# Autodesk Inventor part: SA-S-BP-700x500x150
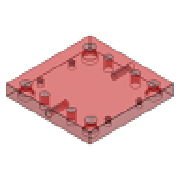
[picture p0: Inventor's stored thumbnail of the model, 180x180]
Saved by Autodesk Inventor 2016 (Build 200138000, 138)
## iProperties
IsCustomPart: 1
Created: 2015-02
Part Number: SA-S-BP-700x500x150
Material: S 55 C
Description: Core Plate
Document SubType Name: Modeling
Designer: Sandeep
Standard Revision: 1
Manufacturer: FUTABA
Language: en-US
Size Designation: 700x500x150
Categories: <MemberInstance><Categories><Category DisplayName="Mold" InternalName="349578f2-f4d4-4954-8c09-8e99297a61c0" Mnemonic="MOLD"><Category DisplayName="Mold Plates"
Density: 7.85 g/cm^3
Appearance: Dark Red
Author: Sandeep
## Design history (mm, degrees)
sketch "Sketch1"
  geometry: L1 (-250, 350)-(250, 350); L2 (250, 350)-(250, -350); L3 (250, -350)-(-250, -350); L4 (-250, -350)-(-250, 350); 7 further points
  constraints: 8 end point, 2 horizontal alignment, 2 midpoint, 2 parallel, 1 horizontal, 1 perpendicular, 1 vertical alignment
  dimensions: "d123" = 500 distance between parallel lines of L2 L4 (= W_); "d124" = 700 distance between parallel lines of L3 L1 (= L); "d125" = 317 vertical distance of point (0, 0) point (-128, 317) (= 0.5 x RP_L); "d126" = 128 horizontal distance of point (0, 0) point (-128, 317) (= 0.5 x RP_W); "d127" = 207 horizontal distance of point (0, 0) point (-207, 307) (= 0.5 x GP_W); "d128" = 307 vertical distance of point (0, 0) point (-207, 307) (= 0.5 x GP_L); "d129" = 205 horizontal distance of point (0, 0) point (-205, 243) (= 0.5 x S1_W); "d130" = 243 vertical distance of point (0, 0) point (-205, 243) (= 0.5 x S1_L); "d140" = 207 horizontal distance of point (207, 307) point (0, 0) (= 0.5 x GP_W)
extrude "Extrusion1" new body sketch "Sketch1" distance "d20" = 150 (= H_); taper "d30" = 0 deg
feature "Sculpt4"
body "Solid1"
sketch "Sketch2"
  geometry: L1 (500, 0)-(0, 0) reference; 3 further points
  constraints: 1 midpoint, 1 vertical alignment
  dimensions: "d186" = 75 distance from line of L1 point (250, 75) (= 0.5 x H_)
hole "Hole1" sketch "Sketch2" diameter "d104" = 31.67; stored, may be unused: countersink angle "d108" = 90 deg, drill point angle "d110" = 118 deg; dims "d105" = 59 (= le), "d106" = 46 (= GP_d2), "d107" = 10 (= GP_k), "d109" = 82 (= ke)
sketch "Sketch3"
  geometry: L1 (0, 0)-(500, 0) reference; 3 further points
  constraints: 1 midpoint, 1 vertical alignment
  dimensions: "d187" = 75 distance from line of point (250, -75) L1 (= 0.5 x H_)
hole "Hole2" sketch "Sketch3" diameter "d113" = 31.67; stored, may be unused: countersink angle "d117" = 90 deg, drill point angle "d119" = 118 deg; dims "d114" = 59 (= le), "d115" = 46 (= GP_d2), "d116" = 10 (= GP_k), "d118" = 82 (= ke)
hole "Hole3" sketch "Sketch1" diameter "d131" = 13.835; stored, may be unused: countersink angle "d135" = 90 deg, drill point angle "d137" = 118 deg; dims "d132" = 20 (= H_l), "d133" = 4, "d134" = 2, "d136" = 30 (= H_u)
pattern_linear "Rectangular Pattern1" dims "d164" = 243 (computed from S1_L, Ns)
hole "Hole4" sketch "Sketch1" diameter "d141" = 40 (= GP_d1); stored, may be unused: countersink angle "d145" = 90 deg, drill point angle "d147" = 0 deg; dims "d142" = 6, "d143" = 46 (= GP_d2), "d144" = 10 (= GP_k), "d146" = 150 (= H_)
pattern_linear "Rectangular Pattern2" dims "d170" = 614 (computed from GP_L, Nl)
hole "Hole5" sketch "Sketch1" diameter "d148" = 40 (= GP_d1); stored, may be unused: countersink angle "d152" = 90 deg, drill point angle "d154" = 0 deg; dims "d149" = 6, "d150" = 46 (= GP_d2), "d151" = 10 (= GP_k), "d153" = 150 (= H_)
pattern_linear "Rectangular Pattern3" dims "d173" = 612 (computed from GP_L2, GP_L1, Nl)
hole "Hole6" sketch "Sketch1" diameter "d155" = 30 (= RP_dt); stored, may be unused: countersink angle "d159" = 90 deg, drill point angle "d161" = 0 deg; dims "d156" = 6, "d157" = 46 (= GP_d2), "d158" = 10 (= GP_k), "d160" = 150 (= H_)
pattern_linear "Rectangular Pattern4" dims "d176" = 634 (computed from RP_L, Nl), "d179" = 256 (computed from RP_W, Nw)
chamfer "Chamfer1" distance "d180" = 0.5; stored, may be unused: second distance "d181" = 2, angle "d182" = 45 deg
feature "Surface4"
body "Srf4"
other parameters: "L" = 700 [user parameter; used in 1 equation term], "W_" = 500 [user parameter; used in 3 equation terms], "H_" = 150 [user parameter; used in 8 equation terms], "GP_W" = 414 [user parameter; used in 2 equation terms], "GP_d1" = 40 [user parameter; used in 2 equation terms], "GP_d2" = 46 [user parameter; used in 5 equation terms], "GP_k" = 10 [user parameter; used in 5 equation terms], "S1_L" = 486 [user parameter; used in 2 equation terms], "GP_L1" = 307 [user parameter; used in 1 equation term], "GP_L2" = 305 [user parameter; used in 1 equation term], "RP_L" = 634 [user parameter; used in 2 equation terms], "RP_W" = 256 [user parameter; used in 2 equation terms], "RP_dt" = 30 [user parameter; used in 1 equation term], "GP_L" = 614 [user parameter; used in 2 equation terms], "d102" = 75 (= 0.5 x H_), "d112" = 75 (= 0.5 x H_), "le" = 59 [user parameter; used in 2 equation terms], "ke" = 82 [user parameter; used in 2 equation terms], "H_l" = 20 [user parameter; used in 1 equation term], "H_u" = 30 [user parameter; used in 1 equation term]
